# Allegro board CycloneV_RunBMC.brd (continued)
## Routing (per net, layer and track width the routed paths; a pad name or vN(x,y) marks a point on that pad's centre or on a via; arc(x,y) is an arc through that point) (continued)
EMMC_SMC_DAT0_CONN: length 65.5
  TOP w0.104: JT1.12 v1(66.26,49.18) ; v1(14.17,36.27) 14.24,36.2 14.38,36.2 14.48,36.1 RT139.1
  L8-SIG w0.076: v1(14.17,36.27) 14.17,36.38 14.65,36.86 14.65,46.05 16.31,47.71 49.33,47.71 49.69,48.06 65.14,48.06 v1(66.26,49.18)
EMMC_SMC_DAT0_R: length 1.6
  TOP w0.104: v1(12.98,32.47) 12.98,32.86 12.88,32.96 12.56,32.96 RT16.2
  BOTTOM w0.127: UB4.K2 v1(12.98,32.47)
EMMC_SMC_DAT1: length 41.6
  TOP w0.127: UT7.Y19 v1(33.97,23.2)
  L10-SIG w0.076: v1(16.83,23.81) 16.73,23.81 16.31,24.23 16.2,24.23 15.44,23.46 15.33,23.46 15.22,23.56 15.22,23.67 15.99,24.44 15.99,24.55 15.88,24.66 15.77,24.66 15,23.89 14.9,23.89 14.79,24 14.79,24.1 15.56,24.87 15.56,24.98 15.18,25.35 14.42,25.35 13.91,24.85 13.91,24.62 13.99,24.55 14.5,24.55 14.57,24.47 14.57,24.32 14.5,24.24 13.99,24.24 13.91,24.16 13.91,23.32 14.09,23.14 16.1,23.14 16.3,22.94 17.67,22.94 17.82,22.79 18.08,22.79 18.15,22.87 18.15,23.32 18.23,23.4 18.38,23.4 18.46,23.32 18.46,22.87 18.53,22.79 18.69,22.79 18.76,22.87 18.76,23.32 18.84,23.4 18.99,23.4 19.07,23.32 19.07,22.87 19.14,22.79 22.08,22.79 22.16,22.87 22.16,23.35 22.23,23.42 22.38,23.42 22.46,23.35 22.46,22.87 22.54,22.79 22.69,22.79 22.77,22.87 22.77,23.35 22.84,23.42 22.99,23.42 23.07,23.35 23.07,22.87 23.15,22.79 26.44,22.79 26.52,22.87 26.52,23.5 26.6,23.58 26.75,23.58 26.82,23.5 26.82,22.87 26.9,22.79 28.92,22.79 29.22,22.5 29.22,22.39 28.93,22.1 28.93,21.99 29.04,21.89 29.15,21.89 29.43,22.17 29.54,22.17 29.69,22.03 33.32,22.03 33.55,22.26 33.55,22.78 v1(33.97,23.2)
  BOTTOM w0.112: v1(16.83,23.81) 16.39,23.36 RB84.1 15.53,23.55 RB143.1
EMMC_SMC_DAT1_R: length 41
  BOTTOM w0.112: UB4.N2 13.22,29.97 13.58,30.33 13.58,35.66 13.69,35.77 15.58,35.77 15.72,35.63 15.72,35.39 15.6,35.28 14.43,35.28 14.32,35.17 14.32,34.95 14.43,34.83 15.6,34.83 15.72,34.72 15.72,34.5 15.6,34.39 14.43,34.39 14.32,34.28 14.32,34.05 14.43,33.94 15.6,33.94 15.72,33.83 15.72,33.6 15.6,33.49 14.43,33.49 14.32,33.38 14.32,33.16 14.43,33.05 15.6,33.05 15.72,32.93 15.72,32.65 15.83,32.54 16.34,32.54 16.45,32.42 16.45,32.2 16.34,32.09 15.83,32.09 15.72,31.98 15.72,31.75 15.83,31.64 16.34,31.64 16.45,31.53 16.45,31.31 16.34,31.2 15.83,31.2 15.72,31.08 15.72,30.01 15.83,29.9 16.8,29.9 16.91,29.79 16.91,29.57 16.8,29.45 15.83,29.45 15.72,29.34 15.72,29.12 15.83,29.01 16.8,29.01 16.91,28.89 16.91,28.67 16.8,28.56 15.83,28.56 15.72,28.45 15.72,28.22 15.83,28.11 16.8,28.11 16.91,28 16.91,27.78 16.8,27.67 15.83,27.67 15.72,27.55 15.72,26.74 15.6,26.63 14.58,26.63 14.47,26.51 14.47,26.29 14.58,26.18 15.6,26.18 15.72,26.07 15.72,25.84 15.6,25.73 14.58,25.73 14.47,25.62 14.47,25.4 14.58,25.28 15.6,25.28 15.72,25.17 RB84.2
EMMC_SMC_DAT2: length 80
  TOP w0.104: RT11.1 11.5,34.34 11.52,34.31 RT15.1 11.08,33.88 10.97,33.77 v1(10.97,33.41)
  TOP w0.127: UT7.AE25 v1(37.97,28)
  L3-SIG w0.076: v1(37.97,28) 38.55,28 40.18,29.62 40.18,31.81 41.45,33.08 43.68,33.08 45.38,34.78 45.38,42.88 44.47,43.8 44.47,46.84 43.76,47.55 13.99,47.55 10.43,44 10.43,39 10.36,38.92 8.65,38.92 8.58,38.85 8.58,38.69 8.65,38.62 10.36,38.62 10.43,38.54 10.43,38.39 10.36,38.31 8.65,38.31 8.58,38.24 8.58,38.08 8.65,38.01 10.36,38.01 10.43,37.93 10.43,33.95 v1(10.97,33.41)
EMMC_SMC_DAT2_R: length 1.6
  TOP w0.104: RT15.2 11.52,32.55 11.6,32.47 v1(11.98,32.47)
  BOTTOM w0.127: UB4.K3 v1(11.98,32.47)
EMMC_SMC_DAT3: length 79.1
  TOP w0.104: v1(12.84,26.44) 12.45,26.44 12.36,26.53 RT41.1 12.01,26.99 RT43.1
  TOP w0.127: UT7.Y17 v1(33.95,21.58)
  L10-SIG w0.076: v1(33.95,21.58) 33.56,21.19 31.18,21.19 31.1,21.11 31.1,20.68 31.03,20.6 30.88,20.6 30.8,20.68 30.8,21.11 30.72,21.19 29.53,21.19 29.45,21.11 29.45,20.71 29.38,20.63 29.22,20.63 29.15,20.71 29.15,21.11 29.07,21.19 25.35,21.19 25.27,21.27 25.27,21.8 25.2,21.87 25.04,21.87 24.97,21.8 24.97,21.27 24.89,21.19 22.74,21.19 22.67,21.27 22.67,21.7 22.59,21.77 22.44,21.77 22.36,21.7 22.36,21.27 22.29,21.19 22.13,21.19 22.06,21.27 22.06,21.7 21.98,21.77 21.83,21.77 21.75,21.7 21.75,21.27 21.68,21.19 18.31,21.19 18.23,21.11 17.29,21.11 17.06,21.34 16.4,21.34 16.05,20.99 15.28,20.99 15.06,20.76 15.06,19.89 14.78,19.61 14.41,19.61 14.33,19.69 14.33,22.41 14.26,22.48 14.1,22.48 14.03,22.41 14.03,19.69 13.95,19.61 13.8,19.61 13.72,19.69 13.72,22.41 13.65,22.48 13.5,22.48 13.42,22.41 13.42,19.69 13.34,19.61 13.19,19.61 13.11,19.69 13.11,22.41 13.04,22.48 12.89,22.48 12.81,22.41 12.81,19.69 12.73,19.61 12.58,19.61 12.5,19.69 12.5,22.41 12.43,22.48 12.28,22.48 12.2,22.41 12.2,19.69 12.12,19.61 11.97,19.61 11.9,19.69 11.9,22.41 11.82,22.48 11.67,22.48 11.59,22.41 11.59,19.69 11.51,19.61 11.22,19.61 11.04,19.79 11.04,21.42 10.86,21.6 10.66,21.6 10.59,21.68 10.59,21.83 10.66,21.91 10.86,21.91 10.94,21.98 10.94,22.13 10.86,22.21 10.66,22.21 10.59,22.29 10.59,22.44 10.66,22.52 10.86,22.52 10.94,22.59 10.94,22.74 10.86,22.82 10.66,22.82 10.59,22.9 10.59,23.05 10.66,23.13 10.86,23.13 10.94,23.2 10.94,24.52 10.89,24.57 10.89,25 10.81,25.08 10.03,25.08 9.95,25.16 9.95,25.31 10.03,25.38 10.81,25.38 10.89,25.46 10.89,25.61 10.81,25.69 10.03,25.69 9.95,25.77 9.95,25.92 10.03,25.99 10.81,25.99 10.89,26.07 10.89,26.22 10.81,26.3 10.03,26.3 9.95,26.37 9.95,26.53 10.03,26.6 10.81,26.6 10.89,26.68 10.89,26.78 11.09,26.98 11.96,26.98 12.03,26.9 12.03,25.35 12.11,25.28 12.26,25.28 12.34,25.35 12.34,26.9 12.41,26.98 12.63,26.98 12.84,26.77 v1(12.84,26.44)
EMMC_SMC_DAT3_R: length 2.5
  TOP w0.104: RT41.2 12.46,27.98 12.46,29 v1(11.98,29.47)
  BOTTOM w0.127: UB4.N3 v1(11.98,29.47)
EMMC_SMC_DAT4: length 80.2
  TOP w0.104: v1(6.98,30.68) 7.47,30.18 RT27.1 7.49,30.12 RT21.1
  TOP w0.127: UT7.Y18 v1(33.98,22.41)
  L3-SIG w0.076: v1(33.98,22.41) 33.6,22.79 32.27,22.79 32.03,22.55 32.03,22.39 31.7,22.06 31.53,22.06 31.23,21.75 31.23,21.31 30.14,20.22 29.15,20.22 28.82,20.55 28.82,20.86 28.49,21.19 24.2,21.19 23.93,21.46 23.93,23.35 23.68,23.6 22.27,23.6 21.48,24.39 18.46,24.39 18.31,24.24 16.29,24.24 16.21,24.31 16.21,24.88 16.29,24.96 16.94,24.96 17.01,25.04 17.01,25.19 16.94,25.27 16.29,25.27 16.21,25.34 16.21,25.49 16.29,25.57 16.94,25.57 17.01,25.65 17.01,25.8 16.94,25.88 16.29,25.88 16.21,25.95 16.21,27.18 16.14,27.26 15.98,27.26 15.91,27.18 15.91,24.29 15.83,24.21 15.68,24.21 15.6,24.29 15.6,27.18 15.53,27.26 15.37,27.26 15.3,27.18 15.3,24.29 15.22,24.21 15.07,24.21 14.99,24.29 14.99,27.18 14.92,27.26 14.76,27.26 14.69,27.18 14.69,24.29 14.61,24.21 13.63,24.21 12.57,25.28 12.28,25.28 12.21,25.35 12.21,26.12 12.13,26.19 11.98,26.19 11.9,26.12 11.9,25.35 11.83,25.28 10.6,25.28 10.52,25.35 10.52,25.58 10.44,25.66 10.29,25.66 10.21,25.58 10.21,25.35 10.14,25.28 9.99,25.28 9.91,25.35 9.91,25.58 9.83,25.66 9.68,25.66 9.61,25.58 9.61,25.35 9.53,25.28 9.38,25.28 9.3,25.35 9.3,25.58 9.22,25.66 9.07,25.66 9,25.58 9,25.35 8.92,25.28 8.5,25.28 7.82,25.96 7.13,25.96 7,26.09 7,26.5 6.75,26.75 5.94,26.75 5.86,26.83 5.86,27.49 5.79,27.56 5.63,27.56 5.56,27.49 5.56,26.83 5.48,26.75 5.33,26.75 5.25,26.83 5.25,27.49 5.18,27.56 5.02,27.56 4.95,27.49 4.95,26.83 4.87,26.75 4.34,26.75 3.9,27.18 3.9,27.8 3.98,27.88 4.59,27.88 4.67,27.95 4.67,28.11 4.59,28.18 3.98,28.18 3.9,28.26 3.9,28.46 3.98,28.54 5.1,28.54 5.17,28.61 5.17,28.77 5.1,28.84 3.98,28.84 3.9,28.92 3.9,29.07 3.98,29.15 5.1,29.15 5.17,29.22 5.17,29.38 5.1,29.45 3.98,29.45 3.9,29.53 3.9,29.68 3.98,29.76 5.1,29.76 5.17,29.83 5.17,29.99 5.1,30.06 3.98,30.06 3.9,30.14 3.9,30.46 4.39,30.94 6.71,30.94 v1(6.98,30.68)
EMMC_SMC_DAT4_R: length 1.6
  TOP w0.104: RT27.2 6.58,29.63 6.72,29.5 v1(6.96,29.5)
  BOTTOM w0.127: v1(6.96,29.5) UB4.N8
EMMC_SMC_DAT5: length 90.9
  TOP w0.104: v1(9.31,26.89) 8.91,27.29 8.91,27.89 9.14,28.12 9.14,31.86 8.32,32.67 8.32,33.13 8.08,33.37 RT98.1 7.26,33.37 RT18.1
  TOP w0.127: UT7.AB23 v1(35.55,26.38)
  L5-SIG w0.076: v1(35.55,26.38) 35.98,26.81 36.62,26.81 36.8,26.99 36.8,27.34 37.07,27.62 38.17,27.62 38.6,28.05 40.68,28.05 40.84,27.89 42.31,27.89 44.22,29.8 44.22,32.32 45.05,33.15 45.05,35.44 45.86,36.25 45.86,40.39 46.46,40.98 46.46,44.17 45.74,44.89 45.74,46.28 44.82,47.21 16.23,47.21 14.04,45.01 12.82,45.01 10.46,42.65 10.46,28.04 v1(9.31,26.89)
EMMC_SMC_DAT5_R: length 1.3
  TOP w0.104: RT18.2 6.08,32.57 v1(5.99,32.47)
  BOTTOM w0.127: UB4.K8 v1(5.99,32.47)
EMMC_SMC_DAT6: length 84.7
  TOP w0.104: RT36.1 7.41,27.72 ; 7.41,27.72 7.42,27.73 RT30.1 ; 7.41,27.72 7.37,27.72 v1(7.01,28.08)
  TOP w0.127: UT7.AA24 v1(33.99,26.42)
  L3-SIG w0.076: v1(33.99,26.42) 34.27,26.7 34.28,26.7 34.34,26.76 34.34,27.27 34.63,27.55 38.44,27.55 42.05,31.17 42.61,31.17 45.69,34.24 45.69,42.93 45.56,43.06 45.56,43.62 45.79,43.85 45.79,45.95 43.96,47.78 13.86,47.78 8.93,42.86 8.93,41.48 7.48,40.03 7.48,28.55 v1(7.01,28.08)
EMMC_SMC_DAT6_R: length 1.8
  TOP w0.104: v1(5.92,29.54) 5.92,29.05 6.04,28.94 RT30.2
  BOTTOM w0.127: v1(5.92,29.54) UB4.N9
EMMC_SMC_DAT7: length 82.6
  TOP w0.104: RT99.1 6.5,34.38 6.99,33.89 RT13.1 7.42,33.81 7.55,33.94 8.2,33.94 8.58,33.55 8.58,32.85 9.44,32 9.44,27.95 9.32,27.82 v1(9.32,27.42)
  TOP w0.127: UT7.V16 v1(32.38,20.81)
  L10-SIG w0.076: v1(9.32,27.42) 8.21,27.42 7.92,27.13 7.92,26.87 7.99,26.79 8.68,26.79 8.76,26.72 8.76,26.56 8.68,26.49 7.99,26.49 7.92,26.41 7.92,26.26 7.99,26.18 8.68,26.18 8.76,26.11 8.76,25.96 8.68,25.88 7.99,25.88 7.92,25.8 7.92,25.1 7.99,25.02 8.37,25.02 8.44,25.1 8.44,25.48 8.52,25.56 8.67,25.56 8.75,25.48 8.75,25.1 8.83,25.02 9.54,25.02 9.62,24.95 9.62,24.52 9.67,24.47 9.98,24.47 10.08,24.36 10.08,23.42 9.96,23.3 8.28,23.3 7.87,22.89 7.87,22.66 7.94,22.58 9.85,22.58 9.92,22.5 9.92,22.35 9.85,22.27 7.94,22.27 7.87,22.2 7.87,22.05 7.94,21.97 9.85,21.97 9.92,21.89 9.92,21.74 9.85,21.66 7.94,21.66 7.87,21.59 7.87,21.44 7.94,21.36 9.85,21.36 9.92,21.28 9.92,21.13 9.85,21.06 7.94,21.06 7.87,20.98 7.87,20.45 8.05,20.27 8.98,20.27 9.98,19.28 10.3,19.28 10.37,19.21 10.37,17.94 10.45,17.86 10.6,17.86 10.68,17.94 10.68,19.21 10.75,19.28 10.9,19.28 10.98,19.21 10.98,17.94 11.06,17.86 11.21,17.86 11.29,17.94 11.29,19.21 11.36,19.28 11.51,19.28 11.59,19.21 11.59,17.94 11.67,17.86 11.82,17.86 11.9,17.94 11.9,19.21 11.97,19.28 12.12,19.28 12.2,19.21 12.2,17.94 12.28,17.86 12.43,17.86 12.51,17.94 12.51,19.21 12.58,19.28 12.73,19.28 12.81,19.21 12.81,17.94 12.89,17.86 13.04,17.86 13.11,17.94 13.11,19.21 13.19,19.28 13.34,19.28 13.42,19.21 13.42,17.94 13.5,17.86 13.65,17.86 13.72,17.94 13.72,19.21 13.8,19.28 13.95,19.28 14.03,19.21 14.03,17.94 14.11,17.86 14.26,17.86 14.33,17.94 14.33,19.21 14.41,19.28 15.94,19.28 17.43,20.77 18.04,20.77 18.43,20.38 31.95,20.38 v1(32.38,20.81)
EMMC_SMC_DAT7_R: length 2.8
  TOP w0.104: v1(4.99,32.47) 5.58,33.07 5.58,33.73 5.67,33.81 RT13.2
  BOTTOM w0.127: UB4.K9 v1(4.99,32.47)
EMMC_STRB_R: length 1.7
  TOP w0.104: v1(9.9,32.56) 9.9,32.95 9.73,33.11 RT14.1
  BOTTOM w0.127: UB4.K5 v1(9.9,32.56)
FAN_PWM0: length 18.8
  TOP w0.104: v1(16.81,9.91) 16.54,9.64 16.54,9.62 16.39,9.47 EUT3.20
  L5-SIG w0.076: v1(7.38,5.9) 7.37,5.9 7,6.27 7,6.73 7.01,6.74 8.18,7.92 8.77,7.92 8.91,7.78 11.32,7.78 11.88,8.34 11.88,8.67 12.79,9.58 16.48,9.58 v1(16.81,9.91)
  BOTTOM w0.112: v1(7.38,5.9) 6.93,5.44 6.93,4.52 7.17,4.28 7.42,4.28 7.68,4.02 JT3.26
FAN_PWM1: length 16.3
  TOP w0.104: EUT3.18 v1(16.35,8.67)
  L5-SIG w0.076: v1(7.38,6.43) 7.38,6.78 8.24,7.63 8.56,7.63 8.69,7.5 11.63,7.5 12.31,8.18 15.87,8.18 v1(16.35,8.67)
  BOTTOM w0.112: JT3.28 8.23,1.62 8.23,4.74 7.79,5.18 7.79,6.16 7.52,6.43 v1(7.38,6.43)
FAN_PWM2: length 16.2
  TOP w0.104: v1(8.42,6.69) 8.02,6.28 8.02,5.09 8.22,4.89 8.22,3.17 8.16,3.11 7.93,2.87 JT3.27 ; EUT3.16 16.11,7.87 16.22,7.75 16.23,7.75 16.28,7.7 16.55,7.7 v1(16.96,8.11)
  L5-SIG w0.076: v1(16.96,8.11) 16.58,7.73 16.05,7.73 15.53,7.21 8.95,7.21 v1(8.42,6.69)
FAN_PWM3: length 13.2
  TOP w0.104: v1(15.33,6.78) 15.33,6.79 15.33,6.94 15.23,7.04 14.98,7.04 14.88,6.95 EUT3.14
  L5-SIG w0.076: v1(8.41,6.1) 9.19,6.89 12.53,6.89 12.64,6.78 v1(15.33,6.78)
  BOTTOM w0.112: v1(8.41,6.1) 8.27,6.1 8.03,5.86 8.03,5.28 8.48,4.83 8.48,3.17 8.68,2.97 JT3.30
FAN_PWM4: length 11.5
  TOP w0.104: v1(8.42,5.54) 8.46,5.5 8.46,2.91 8.43,2.88 JT3.29 ; v1(14.08,6.09) EUT3.12
  L5-SIG w0.076: v1(8.42,5.54) 9.25,4.71 11.41,4.71 11.6,4.91 11.6,5.39 11.88,5.67 13.66,5.67 v1(14.08,6.09)
FAN_PWM5: length 10.9
  TOP w0.104: v1(13.3,6.08) 13.3,6.08 13.28,6.1 EUT3.10
  BOTTOM w0.112: v1(13.3,6.08) 12.49,6.89 9.01,6.89 8.81,6.69 8.81,6.53 8.81,6.52 8.81,5.05 8.72,4.96 8.72,3.32 9.18,2.86 JT3.32
FAN_TACH0: length 10.9
  TOP w0.104: v1(16.99,8.67) 16.59,9.07 EUT3.19
  L5-SIG w0.076: v1(16.99,8.67) 18.33,7.32 19.27,7.32 19.91,6.69 19.91,5.28 v1(20.31,4.88)
  BOTTOM w0.112: JT3.78 20.68,2.88 20.85,3.05 20.85,3.95 20.31,4.49 v1(20.31,4.88)
FAN_TACH1: length 11.3
  TOP w0.104: EUT3.17 16.22,8.27 16.35,8.13 v1(16.38,8.13)
  BOTTOM w0.112: v1(16.38,8.13) 16.02,7.77 16.02,6.99 17.37,5.64 18.1,5.64 18.45,5.3 20.51,5.3 20.82,4.99 20.82,4.43 21.18,4.07 JT3.80
FAN_TACH2: length 11.9
  TOP w0.104: v1(16.41,7.3) 16.4,7.3 16.23,7.47 EUT3.15
  BOTTOM w0.112: JT3.82 21.68,2.81 21.48,3 21.48,4.09 21.78,4.39 21.78,5.66 21.28,6.17 20.21,6.17 19.68,5.64 18.59,5.64 18.32,5.91 17.48,5.91 17.01,6.38 17.01,6.7 v1(16.41,7.3)
FAN_TACH3: length 13.3
  TOP w0.104: v1(21.91,3.71) 21.91,4.94 21.53,5.31 20.21,5.31 19.98,5.54 19.98,6.57 19.63,6.91 18.16,6.91 18.16,6.92 17.9,6.92 ; EUT3.13 14.48,6.31 14.57,6.23
  TOP w0.114: 14.57,6.23 15.54,6.23 16,6.69 16.35,6.69 16.58,6.92 17.9,6.92
  BOTTOM w0.112: JT3.84 22.18,2.89 22.31,3.02 22.31,3.52 22.12,3.71 v1(21.91,3.71)
FAN_TACH4: length 16.2
  TOP w0.104: EUT3.11 13.68,5.29 14.09,4.88 16.4,4.88 17.47,5.95 v1(17.47,6.5)
  BOTTOM w0.112: v1(17.47,6.5) 17.52,6.5 17.62,6.41 17.62,6.37 17.84,6.15 18.48,6.15 18.63,6 19.59,6 20.02,6.43 21.48,6.43 22.04,5.87 22.04,4.83 22.57,4.3 22.57,3.12 22.68,3.02 JT3.86
FAN_TACH5: length 17.6
  TOP w0.104: EUT3.9 12.88,5.76 13.99,4.65 16.5,4.65 16.5,4.65 16.55,4.65 18,6.1 v1(18,6.53)
  BOTTOM w0.112: v1(18,6.53) 18.33,6.86 21.89,6.86 23.14,5.61 23.14,3.72 23.36,3.51 23.36,3.08 23.18,2.9 JT3.88
FM_B2B_BUFFER_OE3_N: length 38.8
  TOP w0.104: v1(52.42,25.51) 52.42,25.56 UT4.B12
  L5-SIG w0.076: v1(40.48,4.15) 40.5,4.15 40.87,4.51 41.56,4.51 41.88,4.19 41.88,2.29 42.28,1.89 43.83,1.89 44.58,2.63 44.58,3.46 44.29,3.75 44.29,5.66 45.61,6.98 45.61,13.48 49,16.87 49.93,16.87 54.1,21.04 54.1,22.76 53.52,23.34 53.52,24.41 v1(52.42,25.51)
  BOTTOM w0.112: v1(40.48,4.15) 40.25,4.15 39.93,3.82 39.93,3.02 39.92,3.02 39.92,3 39.64,2.72 39.64,1.61 JT3.146
FM_B2B_BUFFER_OE4_N: length 43.4
  TOP w0.104: v1(53.41,25.53) 53.41,25.55 UT4.B11
  L5-SIG w0.076: v1(53.41,25.53) 53.01,25.93 52.19,25.93 51.83,25.58 51.83,24.97 52.83,23.98 52.83,23.46 53.29,22.99 53.29,20.71 49.75,17.18 48.96,17.18 45.33,13.54 45.33,7.04 44.05,5.76 44.05,3.65 44.34,3.36 44.34,2.73 43.72,2.11 42.54,2.11 42.13,2.52 42.13,4.39 41.18,5.34 39.92,5.34 39.71,5.13 39.71,4.94 39.72,4.93 v1(39.72,4.88)
  BOTTOM w0.112: 39.44,4.61 37.9,4.61 37.18,3.89 JT3.144
  BOTTOM w0.114: 39.24,4.61 39.24,4.6 ; v1(39.72,4.88) 39.44,4.6
FM_BIOS_POST_CMPLT_N: length 31.8
  TOP w0.127: v1(17.42,21.54) 17.42,21.62 17.8,22.01 UT7.A18
  L3-SIG w0.076: v1(17.42,21.54) 16.93,21.54 16.48,21.09 16.48,20.61 16.48,20.6 16.48,19.74 16.07,19.33 14.37,19.33 13.14,18.11 13.14,16.74 12.24,15.84 12.24,8.79 11.75,8.31 11.75,5.84 11.77,5.83 11.77,5.51 11.75,5.5 11.75,3.26 12.01,3 12.03,3 12.59,2.44 17.53,2.44 17.62,2.53 17.62,2.6 v1(18.18,3.16)
  BOTTOM w0.112: v1(18.18,3.16) JT3.68
FM_BMC_HBIN: length 26.3
  TOP w0.089: UT7.E8 v1(21.96,14.39)
  TOP w0.104: JT3.141 36.43,2.99 36.32,3.1 36.32,3.13 v1(36.29,3.15)
  L3-SIG w0.076: v1(36.29,3.15) 36.29,3.13 36.05,2.89 36.05,2.76 35.2,1.91 30.13,1.91 29.11,2.92 29.11,4.41 28.48,5.05 28.48,6.42 27.7,7.2 27.2,7.7 27.2,11.56 26.82,11.94 24.23,11.94 21.96,14.21 v1(21.96,14.39)
FM_BMC_HBOUT: length 29.7
  TOP w0.089: UT7.D8 v1(21.17,13.62)
  TOP w0.104: v1(36.29,3.69) 36.75,3.69 36.93,3.51 JT3.143
  L3-SIG w0.076: v1(21.17,13.62) 21.56,14.01 21.56,14.69 21.76,14.89 22.12,14.89 22.62,14.38 22.62,14.03 24.25,12.4 27.1,12.4 27.96,11.54 27.96,7.45 29.36,6.05 29.36,3.88 29.34,3.86 29.34,3.01 30.15,2.19 35.01,2.19 35.92,3.11 35.92,3.31 36.29,3.67 v1(36.29,3.69)
FM_BMC_ON: length 89.9
  TOP w0.104: JT3.109 28.43,2.65 28.14,2.95 28.14,3.29 28.39,3.55 v1(28.39,3.63)
  TOP w0.127: UT4.F10 v1(54.38,29.52)
  L3-SIG w0.076: v1(28.39,3.63) 28.13,3.36 28.13,2.97 29.69,1.4 35.86,1.4 36.96,2.51 36.96,4.06 37.78,4.87 38.84,4.87 40.19,3.52 40.19,2.28 41.7,0.77 65.02,0.77 67.02,2.77 67.02,3.41 68.79,5.17 68.79,11.97 68.64,12.12 68.64,16.65 67.94,17.35 67.83,17.39 67.6,17.55 67.4,17.75 67.24,17.98 67.2,18.09 66.49,18.8 66.49,21.57 66.81,21.9 66.81,25.74 66.49,26.07 66.49,28.89 65.96,29.42 65.93,29.45 63.87,29.45 63.52,29.1 62.43,29.1 62.11,29.42 60.77,29.42 60.53,29.17 54.73,29.17 v1(54.38,29.52)
FM_BMC_ONCTL_R_N: length 29.2
  TOP w0.127: UT7.H16 v1(23.58,20.81)
  L8-SIG w0.076: v1(23.58,20.81) 23.26,20.81 22.81,20.36 22.28,20.36 21.02,19.11 20.24,19.11 20.02,18.89 20.02,18.3 19.7,17.99 18.08,17.99 14.98,14.89 14.98,13.85 14.4,13.26 13.63,13.26 12.34,11.97 12.34,10.1 11.64,9.4 11.64,5.93 11.36,5.64 v1(11.22,5.64)
  BOTTOM w0.112: 11.25,5.64 11.37,5.52 11.37,5.46 11.58,5.25 11.58,4.91 11.35,4.68 10.41,4.68 10.1,4.37 10.1,3.03 10.18,2.95 JT3.36
  BOTTOM w0.114: v1(11.22,5.64) 11.65,5.64 RB82.2
FM_BMC_PWRBTN_OUT_N: length 42.9
  TOP w0.089: 40.73,11.26 40.56,11.44 40.56,11.77 40.3,12.02 39.57,12.02 UT7.AG6
  TOP w0.104: v1(39.92,6.91) 40.39,7.38 RT108.2 41.14,7.46 41.14,8.84 41.37,9.07 41.37,10.62 40.73,11.26
  L8-SIG w0.076: v1(11.37,3.54) 11.37,2.25 11.88,1.73 32.61,1.73 33.42,2.55 33.42,3.56 34.18,4.32 34.18,4.81 34.89,5.52 36.29,5.52 37.3,6.52 39.53,6.52 v1(39.92,6.91)
  BOTTOM w0.112: JT3.40 11.18,2.97 11.37,3.15 v1(11.37,3.54)
FM_BOARD_ID: length 44.1
  TOP w0.104: v1(51.91,6.12) 53.08,4.95 53.08,3.79 53.21,3.66 53.21,3.1 53.43,2.88 JT3.201
  TOP w0.127: UT4.F12 v1(52.38,29.52)
  L8-SIG w0.076: v1(51.91,6.12) 51.91,6.43 52.01,6.53 52.02,6.53 52.5,7.02 52.5,8.73 52.42,8.81 52.42,9.68 52.9,10.17 52.9,11.87 51.94,12.83 51.94,14.66 50.91,15.69 50.91,18.2 53.41,20.71 53.41,20.86 53.21,21.06 52.22,21.06 51,22.28 51,23.81 50.85,23.95 50.85,28.55 51.18,28.88 51.74,28.88 v1(52.38,29.52)
  BOTTOM w0.112: v1(52.38,29.52) 52,29.9 51.07,29.9 50.79,29.62 50.41,29.62 49.17,28.38 49.17,27.21 47.53,25.57 RB86.1
FM_C5_BSEL0: length 11.5
  TOP w0.114: v1(15.59,19.96) 15.59,19.69 RB79.2
  TOP w0.127: UT7.J17 v1(24.38,21.61)
  L8-SIG w0.076: v1(24.38,21.61) 23.98,22 18.66,22 18.42,21.76 18.42,21.32 18.15,21.06 17.54,21.06 16.44,19.96 v1(15.59,19.96)
FM_C5_BSEL1: length 1.5
  TOP w0.127: UT7.A6 v1(17.98,12.01)
  BOTTOM w0.114: v1(17.98,12.01) 17.73,12.01 RT20.1
FM_C5_BSEL2: length 2.6
  TOP w0.127: UT7.D15 v1(20.38,20.01)
  BOTTOM w0.114: v1(20.38,20.01) 19.98,20.4 19.14,20.4 18.97,20.57 RT78.1
FM_C5_CONF_DONE: length 45.5
  TOP w0.104: v1(47.49,35.77) 47.9,35.77 48.15,35.51 49.4,35.51 49.88,36 UT4.M15
  TOP w0.127: UT7.J8 v1(24.38,13.61)
  L8-SIG w0.076: v1(24.38,13.61) 24.38,13.8 24,14.18 24,15.47 24.12,15.6 24.5,15.6 25.35,16.45 28.6,16.45 28.85,16.69 28.85,19.21 29.19,19.55 29.19,22.32 29.64,22.77 35.43,22.77 36.26,23.6 37.46,23.6 37.7,23.84 38.82,23.84 39.41,24.44 41.22,24.44 43.94,27.16 43.94,31.63 45.32,33.01 47.35,33.01 47.69,33.36 47.69,35.57 v1(47.49,35.77)
  BOTTOM w0.112: RT28.1 47.06,35.34 v1(47.49,35.77)
FM_C5_CONFIG_N: length 51.3
  TOP w0.127: UT7.F7 v1(21.98,12.81) ; UT4.L12 v1(52.42,34.55)
  L3-SIG w0.076: v1(52.42,34.55) 51.96,35.01 49.35,35.01 48.05,36.3 v1(47.49,36.3)
  L8-SIG w0.076: v1(47.49,36.3) 45.81,36.3 45.21,35.69 45.21,34.65 44.09,33.53 44.09,32.67 42.69,31.27 42.69,26.83 41.11,25.25 36.3,25.25 35.49,24.43 29.67,24.43 29.08,23.83 29.08,23.27 28.65,22.85 28.22,22.85 27.96,22.59 27.96,19.69 27.4,19.13 26.79,19.13 26.36,18.7 26.36,18.17 26.17,17.98 23.44,17.98 23.16,17.7 23.16,16 22.72,15.57 22.72,15.57 22.37,15.22 22.37,13.2 v1(21.98,12.81)
  BOTTOM w0.112: v1(52.42,34.55) 52.42,34.94 52.26,35.1 RB71.1
FM_C5_DEV_OE_N: length 1.2
  TOP w0.127: UT7.AC24 v1(36.38,27.21)
  BOTTOM w0.254: v1(36.38,27.21) 36.25,27.08 RB75.1
FM_C5_FPGA_AS_DATA0: length 41.4
  TOP w0.127: UT7.AD7 v1(37.18,12.81)
  L3-SIG w0.076: v1(50.77,12.28) 49.91,12.28 49.24,11.61 46.04,11.61 44.44,13.21 41.9,13.21 41.62,13.49 39.29,13.49 39.01,13.21 37.58,13.21 v1(37.18,12.81)
  L8-SIG w0.076: v1(50.77,12.28) 50.2,12.85 50.2,16.78 50.36,16.95 50.36,20.83 49.39,21.81 49.39,23.7 49.8,24.11 49.8,24.61 49.26,25.16 49.23,25.16 49.02,25.37 49.02,28.04 v1(48.3,28.76)
  BOTTOM w0.112: RB69.2 48.41,35.9 47.97,35.46 47.97,29.09 v1(48.3,28.76)
FM_C5_FPGA_AS_DATA0_R: length 1.4
  TOP w0.127: UT4.M14 v1(50.42,35.56)
  BOTTOM w0.112: v1(50.42,35.56) 50.12,35.56 RB69.1
FM_C5_FPGA_DCLK: length 32.5
  TOP w0.104: v1(46.07,34.07) 46.37,34.37 46.37,34.98 RT37.2
  TOP w0.127: UT7.AA8 34.91,14.01 35.01,13.9 v1(35.01,13.51)
  L5-SIG w0.076: v1(46.07,34.07) 46.07,31.35 45.31,30.59 45.31,29.37 43.03,27.09 39.91,27.09 39.39,27.62 38.67,27.62 38.42,27.36 38.42,27.05 38.17,26.8 37.84,26.8 37.31,26.28 36.37,26.28 36.16,26.07 36.16,25.9 36,25.75 36,24.65 36.16,24.49 36.16,20.91 35.71,20.45 35.71,14.2 v1(35.01,13.51)
  BOTTOM w0.254: RB135.1 34.28,13.11 34.74,13.57 34.95,13.57 v1(35.01,13.51)
FM_C5_FPGA_DCLK_R: length 1.6
  TOP w0.104: RT37.1 47.33,35.02 UT4.L16
FM_C5_FPGA_MSEL0: length 54.8
  TOP w0.104: RT85.1 RT84.2 64.76,23.8 v1(64.66,23.91) 64.1,24.47 63.43,24.47 UT4.A2
  TOP w0.127: UT7.J10 v1(24.38,15.21)
  L8-SIG w0.076: v1(45.13,24.54) 45.13,24.8 44.82,25.1 44.09,25.1 43.78,24.8 42.7,24.8 41.55,23.65 37.9,23.65 37.62,23.36 37.62,23.05 37.38,22.81 36.52,22.81 35.69,21.98 29.69,21.98 29.51,21.8 29.51,19.23 29.15,18.88 29.15,16.03 28.74,15.62 25.01,15.62 24.59,15.21 v1(24.38,15.21)
  L10-SIG w0.076: v1(45.13,24.54) 45.52,24.93 61.35,24.93 61.82,24.47 61.82,23.45 62.1,23.17 64.46,23.17 64.66,23.37 v1(64.66,23.91)
FM_C5_FPGA_MSEL1: length 54.4
  TOP w0.104: UT4.A3 62.43,24.47 62.98,24.47 63.09,24.36 v1(63.09,23.61) RT83.1 RT73.2
  TOP w0.127: UT7.H9 v1(23.58,14.41)
  L8-SIG w0.076: v1(43.76,23.24) 43.76,23.25 43.73,23.25 43.58,23.4 42.65,23.4 41.26,22.01 41.26,21.98 40.5,21.21 36.24,21.21 35.63,20.6 35.63,20.55 35.43,20.35 35.43,19.79 35.22,19.59 31.16,19.59 30.37,18.8 30.37,14.99 30.19,14.81 29.76,14.81 29.2,14.25 29.2,13.77 28.54,13.11 24.36,13.11 23.97,13.5 23.97,13.8 23.58,14.19 v1(23.58,14.41)
  L10-SIG w0.076: v1(63.09,23.61) 63.09,24.22 62.16,25.15 44.26,25.15 43.76,24.64 v1(43.76,23.24)
FM_C5_FPGA_MSEL2: length 86
  TOP w0.104: v1(62.25,23.6) 62.25,23.52 62.33,23.44 RT75.1 61.61,23.03 RT76.2 61.59,24.31 UT4.A4
  TOP w0.127: UT7.G6 v1(22.78,12.01)
  L3-SIG w0.076: v1(22.78,12.01) 24,10.79 24,10.17 28.23,5.93 28.23,4.99 28.89,4.33 28.89,2.65 29.91,1.63 35.78,1.63 36.75,2.6 36.75,4.15 37.67,5.07 38.96,5.07 40.4,3.62 40.4,2.37 41.79,0.98 64.62,0.98 66.57,2.93 66.57,4.7 66.21,5.06 66.21,6.33 68.42,8.54 68.42,11.89 67.86,12.45 66.67,12.45 66.49,12.63 66.49,15.78 65.3,16.97 65.3,22.71 64.94,23.07 62.79,23.07 v1(62.25,23.6)
FM_C5_FPGA_MSEL3: length 45.8
  TOP w0.104: RT82.2 RT81.1 60.12,24.78 UT4.A5 59.86,25.02 v1(59.33,24.49)
  TOP w0.127: UT7.K10 v1(25.18,15.21)
  L8-SIG w0.076: v1(44.54,24.54) 44.52,24.52 42.89,24.52 41.15,22.77 37.83,22.77 37.62,22.56 37.62,22.33 37.33,22.05 36.18,22.05 35.31,21.17 30.89,21.17 29.84,20.12 29.84,19.16 29.38,18.7 29.38,15.48 28.75,14.85 25.54,14.85 v1(25.18,15.21)
  L10-SIG w0.076: v1(44.54,24.54) 45.12,23.96 47.62,23.96 47.82,24.17 50.84,24.17 51,24 55.08,24 55.8,24.72 58.88,24.72 59.11,24.49 v1(59.33,24.49)
FM_C5_FPGA_MSEL4: length 44.8
  TOP w0.104: UT4.A6 58.64,24.78 v1(58.64,24.36) RT79.2 RT80.1
  TOP w0.127: UT7.K9 v1(25.18,14.41)
  L8-SIG w0.076: v1(25.18,14.41) 25.56,14.03 28.62,14.03 29.62,15.02 29.62,18.56 30.14,19.08 30.14,20.02 30.55,20.43 34.97,20.43 36.34,21.8 37.53,21.8 37.78,22.05 40.86,22.05 42.72,23.91 43.64,23.91 v1(44.3,23.25)
  L10-SIG w0.076: v1(58.64,24.36) 55.82,24.36 55.27,23.81 50.93,23.81 50.76,23.98 49.21,23.98 48.23,22.99 44.56,22.99 v1(44.3,23.25)
FM_C5_INIT_DONE: length 25.7
  TOP w0.104: UT4.A8 56.58,24.72 RT87.2 55.99,22.8 v1(55.85,22.66)
  TOP w0.127: UT7.AA20 v1(34.78,24.01)
  L10-SIG w0.076: v1(34.78,24.01) 35.16,23.63 42.03,23.63 43,22.66 48.3,22.66 48.71,23.07 55.31,23.07 55.72,22.66 v1(55.85,22.66)
FM_C5_M10_RSVD<0>: length 31.8
  TOP w0.127: UT4.L9 55.88,35.07 56.33,35.51 v1(56.33,35.52) ; UT7.AB26 v1(34.79,28.02)
  L10-SIG w0.076: v1(34.79,28.02) 35.2,27.62 38.7,27.62 40.26,29.17 40.26,29.78 41.01,30.54 42.49,30.54 44.91,32.96 44.91,36.54 46.27,37.9 47.34,37.9 48.25,36.99 54.6,36.99 54.86,36.73 54.86,35.31 55.02,35.15 56.07,35.15 56.33,35.41 v1(56.33,35.52)
FM_C5_M10_RSVD<1>: length 30.4
  TOP w0.127: UT7.W20 33.15,23.98 33.19,23.98 33.22,24.01 v1(33.22,24.01) ; UT4.L10 v1(54.38,35.52)
  L10-SIG w0.076: v1(33.22,24.01) 32.84,24.4 32.84,25.05 33.01,25.23 40.68,25.23 44.16,28.71 44.16,28.94 46.75,31.53 46.75,34.68 47.08,35.01 52.7,35.01 53.21,35.52 v1(54.38,35.52)
FM_C5_M10_RSVD<2>: length 31.4
  TOP w0.104: UT4.M10 55.37,35.53 v1(55.37,35.52)
  TOP w0.127: UT7.AA26 v1(34.73,28.76)
  L10-SIG w0.076: v1(55.37,35.52) 55.72,35.87 55.72,36.81 55.44,37.09 55.14,37.09 54.91,37.32 54.91,37.65 54.6,37.95 47.75,37.95 47.49,38.21 45.94,38.21 44.57,36.84 44.57,32.92 42.44,30.79 40.63,30.79 40.02,30.18 40.02,29.38 39.02,28.38 35.11,28.38 v1(34.73,28.76)
FM_C5_M10_RSVD<3>: length 29.2
  TOP w0.104: UT4.M11 54.38,36.52 v1(54.38,36.52)
  TOP w0.127: v1(33.14,26.42) 33.15,26.42 33.19,26.42 UT7.Y24
  L10-SIG w0.076: v1(54.38,36.52) 53.99,36.12 48.76,36.12 48,35.36 46.7,35.36 46.48,35.13 46.48,31.55 41.65,26.73 40.76,26.73 40.02,25.99 33.57,25.99 v1(33.14,26.42)
FM_C5_STATUS_N: length 44
  TOP w0.104: UT4.L15 49.88,34.88 49.55,34.55 47.54,34.55 v1(47.29,34.3)
  TOP w0.127: UT7.H8 v1(23.58,13.61)
  L8-SIG w0.076: v1(47.29,34.3) 46.48,33.48 45.31,33.48 43,31.17 43,26.64 41.28,24.92 39.46,24.92 38.93,24.39 36.2,24.39 35.39,23.58 29.76,23.58 28.87,22.69 28.87,19.64 28.02,18.78 28.02,17.46 27.8,17.25 24.23,17.25 23.97,16.99 23.97,15.89 23.68,15.6 23.39,15.6 23.22,15.43 23.22,13.97 v1(23.58,13.61)
  BOTTOM w0.112: RT34.1 47.24,34.3 v1(47.29,34.3)
FM_CPLD_HOLD_N: length 27.7
  TOP w0.104: 34.8,6.99 34.8,5.64 34.59,5.43 34.38,5.43 ; RT123.2 34.26,4.41 33.7,3.85 33.7,3.11 33.8,3.01 33.8,3 33.93,2.87 JT3.131
  TOP w0.114: 34.38,5.43 RT123.2 ; v1(35.33,7.7) 34.8,7.17 34.8,6.99
  TOP w0.127: UT7.AC23 v1(35.55,25.58)
  L5-SIG w0.076: v1(35.55,25.58) 35.76,25.38 35.76,24.31 35.91,24.16 35.91,21.29 35.45,20.83 35.45,14.46 34.65,13.66 34.65,12.95 33.55,11.84 33.55,10.17 33.75,9.97 34.13,9.97 34.41,9.69 34.41,8.62 v1(35.33,7.7)
FM_CPU_BMC_MSMI_CATERR_LVT3_N: length 31.2
  TOP w0.104: v1(9.9,5.52) 9.9,3.41 10.43,2.88 JT3.37
  TOP w0.127: UT7.H17 v1(23.58,21.61)
  L8-SIG w0.076: v1(23.58,21.61) 22.1,21.61 21.74,21.24 21.74,20.73 21.41,20.4 18.56,20.4 18.15,20 17.46,20 16.82,19.36 14.62,19.36 13.86,18.6 13.86,16.03 11.86,14.03 11.86,10.3 11.02,9.46 11.02,7.73 10.25,6.97 9.87,6.97 9.52,6.61 9.52,5.9 v1(9.9,5.52)
FM_CPU_BMCINIT: length 35.8
  TOP w0.104: v1(51.34,4.91) 51.72,4.91 51.93,4.7 JT3.195
  TOP w0.127: UT7.AH22 v1(40.38,25.61)
  L3-SIG w0.076: v1(40.38,25.61) 41.9,25.61 42.39,26.09 47.16,26.09 47.72,25.53 v1(48.35,25.53)
  L8-SIG w0.076: v1(51.34,4.91) 51.34,5.4 50.89,5.85 50.89,7.02 50.38,7.53 50.38,8.08 50.59,8.29 50.59,10.54 49.96,11.18 49.96,12.58 49.36,13.17 49.36,16.43 50.12,17.19 50.12,20.62 49.39,21.35 49.39,21.37 48.63,22.14 48.63,23.11 49.02,23.5 49.02,24.87 v1(48.35,25.53)
FM_CPU_ERR2_LVT3_N: length 14.2
  TOP w0.104: JT3.79 20.93,3.61 20.72,3.82 19.88,3.82 19.04,4.65 19.04,5.62 19.48,6.05 v1(19.48,6.43)
  TOP w0.127: UT7.A7 v1(17.98,12.81)
  L3-SIG w0.076: v1(19.48,6.43) 19.48,6.91 19.17,7.22 19.17,12.2 18.97,12.4 18.39,12.4 v1(17.98,12.81)
FM_DEDI_IO3: length 37.1
  L5-SIG w0.076: v1(67.38,32.19) 67.35,32.19 67.04,31.88 66.47,31.88 65.83,32.52 65.83,35.21 66.36,35.74 66.95,35.74 66.98,35.77 v1(67.37,35.77) 67.37,36.95 66.26,38.05 59.84,38.05 57.47,35.69 57.47,35.18 56.7,34.41 56.7,31.23 56.05,30.59 56.05,24.49 56.54,24 56.54,23.26 56.33,23.05 55.11,23.05 v1(54.69,23.46)
  BOTTOM w0.112: TP8.1 67.91,31.65 v1(67.38,32.19) ; RB101.1 54.95,24 54.69,23.74 v1(54.69,23.46) ; RB18.2 v1(67.37,35.77)
FM_DS1818_EN: length 9.3
  BOTTOM w0.254: Q3L1.3 6.19,45.85 5.94,46.11 CB1.1 5.76,47.39 4.86,48.29 Q6A1.2 ; Q3L1.3 6.8,45.01 7.93,46.13 Q7A1.2 ; Q3L1.3 5,45.01 RB31.2
FM_DS1818_EN_G: length 2.9
  BOTTOM w0.254: Q3L1.5 7.46,44.36 7.2,44.1 7.2,43.92 7.42,43.71 Q3L1.6 8.97,43.71 8.98,43.72
FM_DUMP_ALERT_N: length 70.4
  TOP w0.104: v1(7.82,4.5) 7.92,4.4 7.92,3.2 7.43,2.71 JT3.25 ; UT4.A12 v1(52.88,24.52)
  L3-SIG w0.076: v1(46.86,24.34) 47.03,24.17 48.53,24.17 48.68,24.01 52.37,24.01 v1(52.88,24.52)
  L8-SIG w0.076: v1(7.82,4.5) 7.82,3.66 9.99,1.49 33.23,1.49 34.6,2.86 34.6,4.05 34.42,4.22 34.42,4.67 35.05,5.29 36.41,5.29 37.4,6.28 42.23,6.28 42.49,6.53 42.49,7.65 42.97,8.13 42.97,11.16 42.79,11.33 42.79,11.6 46.22,15.02 46.22,17.33 45.78,17.77 45.78,19.61 46.86,20.68 v1(46.86,24.34)
  BOTTOM w0.112: RT71.2 52.88,24.09 v1(52.88,24.52)
FM_EXT_PWR_MODE: length 38
  TOP w0.127: UT7.AF22 v1(38.78,25.61)
  L5-SIG w0.076: v1(38.78,25.61) 39.59,24.8 40.35,24.8 40.86,24.29 40.86,21.19 41.01,21.04 41.01,14.5 41.65,13.86 41.65,12.35 41.22,11.92 40.77,11.92 40.66,11.8 40.66,11 40.89,10.78 41.12,10.78 41.45,10.44 41.45,8.24 41.08,7.87 41.08,6.83 40.5,6.25 37.71,6.25 36.64,5.18 34.65,5.18 34.31,4.84 34.31,4.14 34.61,3.83 34.61,2.99 34.38,2.75 30.9,2.75 30.72,2.93 v1(30.72,3.29)
  BOTTOM w0.112: JT3.118 30.68,3.25 v1(30.72,3.29)
FM_FAN0_PRSNT_N: length 20.1
  TOP w0.127: v1(15.97,12.91) 15.57,12.91 15.44,13.04 EUT1.1
  L3-SIG w0.076: v1(15.97,12.91) 15.84,12.91 15.66,12.73 15.66,12.21 15.67,12.19 15.67,7.47 16.21,6.92 16.32,6.92 16.57,6.67 16.57,6.22 17.13,5.66 17.89,5.66 19.07,4.48 23.06,4.48 23.51,4.93 v1(23.77,4.93)
  BOTTOM w0.112: JT3.94 24.68,2.58 24.56,2.7 24.56,2.76 24.31,3.01 24.31,4.41 24.08,4.63 24.07,4.63 23.78,4.93 v1(23.77,4.93)
FM_FAN1_PRSNT_N: length 20.9
  TOP w0.127: v1(16.05,12.37) 16.12,12.45 16.12,12.45 16.38,12.71 16.38,13.29 15.89,13.77 15.84,13.77 15.72,13.89 EUT1.2
  L3-SIG w0.076: v1(16.05,12.37) 15.89,12.21 15.89,7.99 16.12,7.75 16.48,7.75 16.78,7.45 16.78,6.33 17.21,5.9 18.11,5.9 18.71,5.29 22.37,5.29 22.47,5.39 23.91,5.39 v1(24.33,4.97)
  BOTTOM w0.112: JT3.96 25.22,1.61 25.22,3.39 24.58,4.03 24.58,4.72 v1(24.33,4.97)
FM_FAN2_PRSNT_N: length 22.5
  TOP w0.127: EUT1.3 15.89,14.39 16.1,14.18 16.1,13.93 16.63,13.4 16.63,13.39 16.67,13.35 16.67,12.44 16.45,12.22 16.45,11.89 16.42,11.86 v1(16.42,11.47)
  L3-SIG w0.076: v1(24.95,4.86) 24.68,5.12 24.68,5.3 23.85,6.13 20.24,6.13 19.65,5.54 18.76,5.54 18.18,6.12 17.29,6.12 17.09,6.33 17.09,7.17 17.36,7.44 17.36,11.09 16.98,11.47 v1(16.42,11.47)
  BOTTOM w0.112: JT3.98 25.68,2.92 25.49,3.1 25.49,4.4 25.04,4.86 v1(24.95,4.86)
FM_FAN3_PRSNT_N: length 22.4
  TOP w0.127: v1(16.88,11.89) 16.88,12.3 16.92,12.34 16.92,13.48 16.35,14.05 16.35,14.67 16.14,14.89 EUT1.4
  L3-SIG w0.076: v1(26.16,3.9) 25.55,4.51 25.55,4.91 24,6.46 20.26,6.46 19.73,5.92 18.79,5.92 18.51,6.2 18.51,6.99 17.6,7.9 17.6,11.31 17.01,11.89 v1(16.88,11.89)
  BOTTOM w0.112: v1(26.16,3.9) 25.77,3.51 25.77,3.18 26.18,2.78 JT3.100
FM_FAN4_PRSNT_N: length 22.3
  TOP w0.127: EUT1.5 16.07,15.39 16.81,14.65 v1(16.81,14.23)
  L3-SIG w0.076: v1(26.16,4.7) 24.07,6.79 20.34,6.79 19.98,7.14 19.98,12.2 19.73,12.45 19.4,12.45 19.17,12.68 19.17,12.98 18.89,13.26 18.56,13.26 18.33,13.49 18.33,13.95 17.92,14.37 17.62,14.37 17.46,14.2 17.21,14.2 17.18,14.23 v1(16.81,14.23)
  BOTTOM w0.112: JT3.102 26.68,2.84 26.59,2.93 26.59,4.27 v1(26.16,4.7)
FM_FAN5_PRSNT_N: length 21.5
  TOP w0.203: EUT1.6 v1(15.44,16.37)
  L3-SIG w0.076: v1(26.99,4.7) 23.13,8.57 23.13,9.75 22.92,9.96 22.65,9.96 22.33,10.28 22.33,10.55 22.12,10.76 21.85,10.76 21.56,11.05 21.56,11.35 20.44,12.46 20.23,12.46 20.03,12.66 20.03,12.88 19.65,13.25 19.43,13.25 19.22,13.46 19.22,13.68 18.93,13.97 18.64,13.97 17.84,14.77 17.41,14.77 15.81,16.37 v1(15.44,16.37)
  BOTTOM w0.112: v1(26.99,4.7) 26.99,4.32 26.87,4.2 26.87,3.03 27.18,2.72 JT3.104
FM_FAN6_PRSNT_N: length 23.3
  TOP w0.203: EUT1.7 14.81,16.69 14.98,16.87 15.38,16.87 15.41,16.91 v1(15.42,16.91)
  L3-SIG w0.076: v1(15.42,16.91) 15.99,16.91 16.32,16.58 16.33,16.58 16.74,16.18 16.74,15.85 17.04,15.55 18.18,15.55 18.44,15.29 18.44,15.05 18.7,14.79 19.75,14.79 20.01,14.53 20.01,13.72 20.53,13.2 20.53,13.15 20.83,12.85 20.83,12.66 21.93,11.56 22.12,11.56 22.43,11.25 22.43,11.06 22.63,10.86 22.82,10.86 23.23,10.45 23.23,10.26 23.53,9.96 23.72,9.96 27.48,6.2 27.48,4.85 v1(27.78,4.55)
  BOTTOM w0.112: JT3.106 27.68,2.88 27.77,2.97 27.77,4.54 v1(27.78,4.55)
FM_FAN7_PRSNT_N: length 31
  TOP w0.203: EUT1.8 v2(14.31,17.3)
  L3-SIG w0.076: v2(14.31,17.3) 14.31,16.32 15.21,15.42 15.21,12.53 15.41,12.32 15.41,7.4 15.79,7.02 15.79,5.26 16.06,4.98 16.73,4.98 16.83,5.09 17.2,5.09 17.21,5.09 17.53,5.09 17.53,5.09 17.62,5.09 18.54,4.17 22.65,4.17 23.33,3.5 23.98,3.5 24.15,3.66 25.01,3.66 25.7,2.97 26.34,2.97 26.61,3.24 26.61,3.49 27.28,4.16 v1(28.48,4.16)
  BOTTOM w0.112: v1(28.48,4.16) 28.12,4.16 28,4.04 28,3.08 28.18,2.9 JT3.108
FM_FORCE_BMC_UPDATE_N: length 35.6
  TOP w0.104: JT3.105 27.43,2.68 27.66,2.9 27.66,3.47 27.75,3.56 27.75,4.04 27.4,4.39 27.4,4.87 v1(27.01,5.26)
  TOP w0.127: UT7.AE24 v1(37.98,27.21)
  L5-SIG w0.076: v1(37.98,27.21) 37.76,27.21 37.13,26.57 36.26,26.57 35.7,26.02 35.3,26.02 34.42,25.13 34.42,22.33 34.08,22 33.67,22 33.58,21.91 33.58,21.46 33.3,21.17 32.93,21.17 32.82,21.06 32.82,20.43 31.9,19.51 31.01,19.51 30.37,18.88 30.37,17.36 30.53,17.2 31.07,17.2 31.18,17.09 31.18,16.59 31.34,16.44 31.66,16.44 31.94,16.16 31.94,15.82 30.9,14.79 29.66,14.79 29.18,14.31 29.18,7.59 27.38,5.79 27.38,5.63 v1(27.01,5.26)
FM_FRU_A2: length 3.2
  BOTTOM w0.112: RB86.2 RB94.1 46.64,21.43 46.52,21.31 UB5.3
FM_HPS_PORSEL: length 2.6
  TOP w0.127: UT7.E18 v1(21.18,22.41)
  BOTTOM w0.254: v1(21.18,22.41) 21.77,21.81 RB99.2 21.94,22.7 RB89.1
FM_IM_MASTER: length 73.6
  TOP w0.104: v1(29.71,3.71) 30.07,3.35 30.07,3.34 30.11,3.3 30.11,2.92 29.93,2.74 JT3.115
  TOP w0.127: UT4.F11 v1(53.38,29.52)
  L3-SIG w0.076: v1(29.71,3.71) 30.98,2.44 34.94,2.44 35.72,3.22 35.72,3.39 35.72,3.4 35.72,3.73 36.06,4.07 36.37,4.07 37.57,5.28 40.93,5.28 41.81,4.39 41.81,2.36 42.87,1.3 58.9,1.3 60.26,2.67 60.26,3.31 v1(59.89,3.69)
  L8-SIG w0.076: v1(53.38,29.52) 54.02,28.88 54.53,28.88 55.14,28.28 55.14,27.21 57.86,24.48 57.86,21.99 59.35,20.5 61.54,20.5 62.1,19.94 62.1,13.11 59.1,10.11 59.1,9.28 58.15,8.33 58.15,5.81 59.89,4.08 v1(59.89,3.69)
FM_JTAG_MUX_SEL: length 34.6
  TOP w0.104: v1(45.99,43.31) 45.99,42.93 45.13,42.07 45.13,32.6 43.23,30.69 43.23,29.83 43.2,29.8 RT24.2 42.89,29.46 42.88,29.45 ST1.4
  L3-SIG w0.076: v1(45.99,43.31) 46.22,43.54 46.22,44.63 46.91,45.32 48.94,45.32 49.62,46 54.79,46 v1(55.24,45.55)
  BOTTOM w0.112: UB3.6 54.04,44.18 54.15,44.28 54.15,45.32 54.37,45.55 v1(55.24,45.55) ; UB2.6 54.04,48.24 54.2,48.09 54.2,47.4 55.24,46.36 v1(55.24,45.55) ; v1(55.24,45.55) 55.4,45.71 U12.1
FM_JTAG_MUX_SEL_SW: length 4.3
  TOP w0.104: ST1.2 42.88,19.83 43.17,19.54 43.17,19.41 43.4,19.18 RT60.2
FM_LED_AMBER_GATE: length 4.9
  TOP w0.104: v1(66.22,33.89) 65.88,33.55 RT42.1 65.47,33.3 65.25,33.53 63.37,33.53 UT4.K2
  BOTTOM w0.112: QB1.2 66.17,33.84 v1(66.22,33.89)
FM_LED_BEEP_BMC: length 15.1
  TOP w0.104: JT3.129 33.43,3.95 33.67,4.2 33.67,4.98 33.09,5.57 33.09,5.69 33.09,5.69 33.09,6.01 33.09,6.01 33.09,7.17 v1(33.24,7.33)
  TOP w0.127: v1(37.98,11.2) 37.98,11.59 38.01,11.63 38.01,11.76 38.1,11.85 38.1,12.13 UT7.AF6
  BOTTOM w0.089: v1(37.98,11.2) 37.45,11.2 36.24,9.99 33.86,9.99 33.62,9.75 33.62,8.74 33.24,8.36 33.24,7.65
  BOTTOM w0.112: 33.24,7.65 v1(33.24,7.33)
FM_LED_GREEN_GATE: length 8.2
  TOP w0.127: UT4.K5 v1(60.38,34.52)
  L3-SIG w0.076: v1(65.37,36) 64.53,36 63.54,35.01 60.87,35.01 v1(60.38,34.52)
  BOTTOM w0.112: v1(65.37,36) 65.58,35.79 RB68.1 66.17,35.78 QB1.5
FM_M10_CONFIG_SEL: length 2.3
  TOP w0.127: UT4.F8 v1(57.38,29.52)
  BOTTOM w0.112: v1(57.38,29.52) 57.29,29.43 RB85.1 55.95,29.43 RB87.2
FM_M10_DEBUG_0: length 53.2
  TOP w0.104: v1(54.43,38.49) 53.89,39.02 UT4.R11 ; v1(67.33,40.11) 66.39,40.11 64.99,41.51 JT1.9
  TOP w0.127: v1(33.22,24.85) UT7.W21
  L3-SIG w0.076: v1(67.33,40.11) 65.25,38.03 54.88,38.03 v1(54.43,38.49)
  L10-SIG w0.076: v1(54.43,38.49) 54.93,37.98 55.54,37.98 56.81,36.71 56.81,35.16 56.56,34.91 54.27,34.91 53.36,33.99 49.62,33.99 44.42,28.78 44.42,28.43 40.44,24.45 33.53,24.45 33.22,24.77 v1(33.22,24.85)
FM_M10_DEBUG_1: length 48.2
  TOP w0.104: UT4.R12 52.88,39.02 v1(52.44,38.59) ; JT1.11 66.26,41.33 66.85,40.75 v1(67.35,40.75)
  TOP w0.127: UT7.AA23 v1(34.78,26.41)
  L3-SIG w0.076: v1(67.35,40.75) 66.98,40.75 65.2,38.97 52.8,38.97 52.44,38.61 v1(52.44,38.59)
  L10-SIG w0.076: v1(34.78,26.41) 34.36,26.83 34.36,28.88 34.67,29.19 38.45,29.19 39.24,29.98 39.24,30.68 39.71,31.15 42.49,31.15 44.3,32.96 44.3,37 45.88,38.58 47.51,38.58 47.87,38.94 51.66,38.94 52.01,38.59 v1(52.44,38.59)
FM_M10_DEBUG_2: length 59.9
  TOP w0.089: UT7.V15 v1(31.6,19.99)
  TOP w0.104: JT1.13 67.53,41.53 v1(67.38,41.38) ; v1(52.37,40.53) UT4.T12
  L3-SIG w0.076: v1(52.37,40.53) 52.89,40.01 65.53,40.01 66.9,41.38 v1(67.38,41.38)
  L10-SIG w0.076: v1(52.37,40.53) 51.79,40.53 50.51,39.25 47.36,39.25 47.12,39.01 45.29,39.01 43.91,37.62 43.91,33.38 43.66,33.13 43.27,33.13 42.87,32.72 37.08,32.72 36.32,31.96 36.32,31.2 35.22,30.1 34.23,30.1 33.85,29.72 33.85,29.7 32.61,28.45 32.33,28.45 31.98,28.1 31.98,23.95 32.36,23.58 34.26,23.58 34.41,23.42 34.41,21.14 33.7,20.43 32.78,20.43 32.34,19.99 v1(31.6,19.99)
FM_M10_DEV_CLR_N: length 2.2
  TOP w0.127: UT4.B10 v1(54.38,25.52)
  BOTTOM w0.112: RB101.2 55.02,24.88 v1(54.38,25.52)
FM_M10_EDGE_RSVD<2>: length 68.1
  TOP w0.104: v1(64.41,35.13) 64.29,35.02 UT4.L1
  L8-SIG w0.076: v1(64.41,35.13) 64.02,34.74 64.02,33.82 66.6,31.24 66.6,30.12 66.62,30.1 66.62,23.38 65.73,22.48 65.73,21.21 67,19.94 67,17.59 67.16,17.43 67.16,15.35 65.98,14.17 65.98,12.1 66.62,11.45 66.62,8.72 66.13,8.24 66.13,4.73 66.57,4.3 66.57,2.44 64.93,0.81 43.96,0.81 42.3,2.47 42.3,3.83 41.92,4.2 41.08,4.2 v1(41.02,4.14)
  BOTTOM w0.112: JT3.148 40.18,2.92 40.18,3.51 40.43,3.76 40.59,3.76 40.6,3.77 40.66,3.77 40.87,3.99 40.87,3.99 v1(41.02,4.14)
FM_M10_EDGE_RSVD<3>: length 69.3
  TOP w0.104: v1(63.39,35.58) 62.88,35.07 UT4.L2
  L8-SIG w0.076: v1(41.45,3.82) 41.83,3.82 42.06,3.59 42.06,2.37 43.86,0.57 65.04,0.57 66.81,2.33 66.81,4.59 66.38,5.02 66.38,7.13 67.07,7.83 67.07,8.42 66.87,8.63 66.87,11.56 66.36,12.07 66.36,14.1 67.37,15.11 67.37,15.22 67.4,15.25 67.4,17.53 67.24,17.69 67.24,20.08 66.67,20.66 66.67,21.95 66.87,22.15 66.87,30.2 66.84,30.22 66.84,31.57 65.42,32.99 65.42,35.35 65.2,35.58 v1(63.39,35.58)
  BOTTOM w0.112: JT3.150 40.68,2.75 40.48,2.95 40.48,2.99 40.47,2.99 40.47,3.31 40.7,3.54 41.09,3.54 41.32,3.76 41.4,3.76 v1(41.45,3.82)
FM_M10_EDGE_RSVD<4>: length 43.3
  TOP w0.104: v1(61.45,35.45) UT4.L3
  L5-SIG w0.076: v1(51.35,6.38) 50.95,6.38 50.38,6.95 50.38,10.55 50.06,10.88 50.06,11.93 50.27,12.15 50.27,13.37 52.23,15.32 55.16,15.32 55.85,16.01 55.85,17.61 58.34,20.1 58.34,22.08 58.85,22.59 59.28,22.59 60.83,24.14 60.83,28.66 62.7,30.53 62.7,33.18 61.79,34.09 61.79,35.11 v1(61.45,35.45)
  BOTTOM w0.112: v1(51.35,6.38) 50.82,5.85 50.82,3.08 50.68,2.94 JT3.190
FM_M10_EDGE_RSVD<5>: length 42.6
  TOP w0.104: UT4.M3 v1(62.36,35.54)
  L5-SIG w0.076: v1(62.36,35.54) 62.45,35.54 62.74,35.26 62.74,33.98 62.99,33.74 62.99,30.49 61.74,29.24 61.74,26.67 61.75,26.66 61.75,26.05 61.59,25.89 61.59,25.3 61.13,24.85 61.13,23.75 59.61,22.23 59,22.23 58.59,21.82 58.59,19.82 56.18,17.4 56.18,15.89 55.2,14.92 52.77,14.92 52.1,14.24 52.1,12.62 52.44,12.27 52.44,9.39 52.44,9.39 52.44,8.67 52.62,8.49 52.62,7.14 52.31,6.83 52.31,5.98 51.83,5.5 51.83,4.47 51.74,4.37 v1(51.35,4.37)
  BOTTOM w0.112: JT3.192 51.18,2.66 51.68,3.16 51.68,4.04 v1(51.35,4.37)
FM_M10_EDGE_RSVD<6>: length 49.7
  TOP w0.104: UT4.L6 v1(59.38,35.52)
  L5-SIG w0.076: v1(59.38,35.52) 59.86,36 62.47,36 62.98,35.48 62.98,34.23 64.13,33.08 64.13,30.94 63.01,29.83 63.01,28.46 63.05,28.43 63.05,26.31 62.86,26.12 62.43,26.12 61.87,25.56 61.87,25.13 61.49,24.75 61.49,23.09 62.69,21.89 62.69,20.9 62.1,20.3 62.1,19.16 61.49,18.55 57.93,18.55 56.48,17.1 56.48,15.86 55.21,14.59 52.9,14.59 52.36,14.04 52.36,12.7 52.85,12.21 52.85,10.19 53.23,9.81 53.23,6.09 52.43,5.29 v1(52.43,4.75)
  BOTTOM w0.112: JT3.194 51.71,1.6 51.71,2.85 51.94,3.08 51.94,3.43 51.94,3.43 51.94,4.26 52.05,4.37 52.05,4.38 52.28,4.6 52.28,4.6 v1(52.43,4.75)
FM_M10_EDGE_RSVD<7>: length 47.6
  TOP w0.104: v1(63.39,36.53) 62.88,36.02 UT4.M2
  L5-SIG w0.076: v1(63.39,36.53) 63.82,36.1 63.82,34.22 64.43,33.62 64.43,28.68 63.95,28.2 63.95,26.61 61.79,24.46 61.79,23.14 63.06,21.87 63.06,20.96 62.45,20.35 62.45,18.17 61.49,17.2 57.37,17.2 56.74,16.57 56.74,15.75 55.31,14.33 55.31,13.95 53.46,12.1 53.46,10.67 53.71,10.42 53.71,6.83 54.43,6.11 54.43,5.75 54.92,5.25 54.92,4.78 54.71,4.56 54.39,4.56 54.18,4.36 54.18,3.9 54.07,3.79 53.25,3.79 52.83,4.22 v1(52.44,4.22)
  BOTTOM w0.112: JT3.196 52.18,2.88 52.18,2.89 52.18,3.01 52.17,3.01 52.17,3.33 52.18,3.33 52.18,3.95 v1(52.44,4.22)
FM_M10_JTAGEN: length 20.4
  TOP w0.104: v1(44.75,31.04) 44.06,31.04 43.81,30.79 43.81,29.9 43.86,29.85 RT25.1 44.16,29.43 44.15,29.42 ST1.3
  TOP w0.127: UT4.G6 v1(59.38,30.52)
  L3-SIG w0.076: v1(59.38,30.52) 58.9,31 58.9,31.6 58.62,31.88 48.18,31.88 47.85,31.54 47.85,31.53 47.36,31.04 v1(44.75,31.04)
FM_M10_JTAGEN_SW: length 2.2
  TOP w0.104: ST1.1 45.28,20.99 45.73,20.54 RT58.2
FM_P0V75_AUX_EN_R: length 2.1
  BOTTOM w0.254: EU8F1.7 47.69,46.06 47.24,46.51 C8F8.1 R8F8.2
FM_P3V3_AUX_IO_G: length 2.3
  TOP w0.104: CT14.1 2.44,23.91 RT50.2 2.13,24.86 2.13,25.3 2.32,25.5 UT3.3
FM_PCH_BMC_THERMTRIP_N: length 26.2
  TOP w0.104: JT3.35 9.93,2.92 9.52,3.33 9.52,3.67 9.14,4.04 v1(9.14,4.04)
  TOP w0.127: UT7.A17 v1(17.98,21.61)
  L8-SIG w0.076: v1(17.98,21.61) 17.98,21.75 17.75,21.98 17.27,21.98 16.17,20.88 15.16,20.88 13.63,19.36 13.63,17.15 13.61,17.13 13.61,17.12 11.62,15.13 11.62,13.09 10.81,12.29 10.81,12.03 10.14,11.36 10.14,7.57 9.32,6.75 9.32,4.22 v1(9.14,4.04)
FM_PGPPA_AUX_IO_G: length 3
  TOP w0.104: UT2.3 15.83,28.18 15.09,27.45 RT39.2 CT10.1
FM_PVCCIN_CPU0_PWR_IN_ALERT_N: length 49.2
  TOP w0.127: v1(40.81,26.04) 41.09,25.76 41.09,24.87 40.63,24.41 UT7.AH21
  L8-SIG w0.076: v1(40.81,26.04) 36.21,26.04 36.04,25.86 36.04,25.41 35.84,25.21 29.41,25.21 28.64,24.44 28.3,24.44 27.96,24.1 27.96,23.81 27.73,23.58 27.44,23.58 27.15,23.29 27.15,19.79 27,19.65 26.59,19.65 25.83,18.88 23.49,18.88 21.58,16.97 21.58,15.75 21.41,15.58 21.03,15.58 20.75,15.29 20.75,14.92 20.62,14.79 20.25,14.79 19.96,14.5 19.96,14.18 19.82,14.04 18.65,14.04 18.37,13.76 18.37,10.05 17.53,9.21 17.53,8.08 17.18,7.73 17.13,7.73 17.12,7.72 16.28,7.72 16,7.43 16,6.46 v1(16.17,6.28)
  BOTTOM w0.112: JT3.72 19.18,4.14 17.93,5.39 17.14,5.39 16.25,6.28 v1(16.17,6.28)
FM_PVCCIN_CPU1_PWR_IN_ALERT_N: length 32.9
  TOP w0.104: JT3.117 30.43,2.88 30.35,2.97 30.35,3.13 30.34,3.13 30.34,3.72 30.13,3.93 v1(30.13,4.83)
  TOP w0.127: UT7.AD23 v1(37.18,25.61)
  L5-SIG w0.076: v1(37.18,25.61) 37.59,25.2 37.59,24.54 37.46,24.41 36.98,24.41 36.74,24.18 36.74,19.31 36.37,18.94 36.37,14.16 35.78,13.58 35.78,13.19 35.15,12.55 35.15,10.27 35.43,9.99 35.73,9.99 35.99,9.73 35.99,8.54 36.29,8.24 36.29,7.52 36.09,7.33 34.55,7.33 34.32,7.55 33.62,7.55 33.32,7.85 31.42,7.85 30.91,7.34 30.91,6.82 30.13,6.03 v1(30.13,4.83)
FM_SI5338_SMB_A0: length 1.6
  TOP w0.104: EU5C1.3 48.99,11.84 48.86,11.97 v1(48.86,12.03)
  BOTTOM w0.112: v1(48.86,12.03) 48.86,11.27 R5C13.1
FM_SKT0_FAULT_LED: length 117
  TOP w0.127: v1(47.31,33.53) 49.4,33.53 UT4.K15
  L5-SIG w0.076: v1(10.59,4.17) 10.84,4.17 10.97,4.04 10.97,3.26 10.69,2.98 6.98,2.98 6.62,3.33 6.62,5.23 4.41,7.44 4.41,9.92 5.48,10.99 5.48,14.71 5.99,15.22 5.99,17.2 7.29,18.5 7.29,19.43 6.86,19.86 6.86,24.54 5.86,25.53 5.86,26.4 4.65,27.61 4.65,31.8 3.27,33.18 3.27,46.69 4.11,47.53 46.1,47.53 47,46.63 47,38.54 46.37,37.92 46.37,36.63 46.98,36.02 46.98,34.54 46.9,34.46 46.9,34.14 46.98,34.05 46.98,33.86 v1(47.31,33.53)
  BOTTOM w0.112: v1(10.59,4.17) 10.83,4.17 10.94,4.06 10.94,3.15 10.68,2.88 JT3.38
FM_SLPS4_N: length 29.5
  TOP w0.127: UT7.AE23 v1(37.98,26.41)
  L5-SIG w0.076: v1(37.98,26.41) 37.56,25.99 37,25.99 36.8,25.79 36.8,24.57 36.53,24.3 36.53,20.82 35.96,20.25 35.96,14.18 35.48,13.7 35.48,13.32 34.36,12.2 34.36,10.21 34.56,10.01 34.88,10.01 35.17,9.73 35.17,8.44 v1(35.91,7.7)
  L5-SIG w0.089: 37.98,26.4 v1(37.98,26.41)
  BOTTOM w0.112: v1(35.91,7.7) 35.53,7.33 35.04,7.33 34.77,7.05 34.77,6.65 34.61,6.49 34.61,4.48 34.95,4.14 35.28,4.14 35.66,3.76 35.66,3.43 35.67,3.43 35.67,2.9 35.67,2.89 35.67,2.83 35.68,2.82 JT3.138
FM_SW_ON: length 60.5
  TOP w0.104: v1(27.86,5.09) 28.16,4.78 28.16,4.39 27.98,4.21 27.98,3.47 27.89,3.37 27.89,2.81 27.83,2.75 27.83,1.67 JT3.107
  TOP w0.127: UT4.E11 v1(53.38,28.52)
  L5-SIG w0.076: v1(27.86,5.09) 27.77,5.09 27.39,4.71 27.39,4.29 26.89,3.78 26.89,3.02 27.63,2.27 35.15,2.27 35.68,2.8 35.68,3.89 35.88,4.09 36.28,4.09 37.35,5.17 37.82,5.64 41.55,5.64 42.46,4.73 42.46,2.72 42.64,2.55 43.28,2.55 43.53,2.8 43.53,5.58 45.03,7.08 45.03,13.62 48.84,17.43 49.55,17.43 50.58,18.46 50.58,21.07 51.8,22.3 51.8,22.74 51.83,22.77 51.83,24.23 51.86,24.26 51.86,24.57 50.92,25.51 50.92,27.67 51.28,28.02 52.88,28.02 v1(53.38,28.52)
FM_TPM_EN_PULSE: length 22.6
  TOP w0.104: v1(24.71,3.2) 24.43,2.93 JT3.93
  TOP w0.127: UT7.AH4 v1(39.56,10.39)
  L8-SIG w0.076: v1(39.56,10.39) 39.14,9.97 38.63,9.97 38.37,9.72 38.37,9.4 38.12,9.15 34.64,9.15 34.63,9.15 34.61,9.15 34.42,8.96 34.42,8.73 34.13,8.45 33.76,8.45 32.81,7.5 32.81,6.99 32.23,6.41 30.93,6.41 29.71,5.19 29.71,4.6 29.3,4.2 29.3,2.72 29.04,2.46 25.46,2.46 v1(24.71,3.2)
FM_USB2A_PWREN: length 3.9
  TOP w0.104: JT3.213 56.43,2.91 56.28,3.05 56.28,3.15 56.28,3.15 56.28,4.83 56.13,4.98 R390.2
FM_USBPHY_PCH_CPEN: length 6.8
  TOP w0.104: U8A6.17 59.83,8.57 60,8.4 60,8.25 v1(59.58,7.83) ; v1(56.38,6.48) 56.13,6.23 R390.1
  L10-SIG w0.076: v1(59.58,7.83) 56.28,7.83 55.96,7.51 55.96,6.9 v1(56.38,6.48)
FM_USBPHY_PCH_ID: length 1.5
  TOP w0.104: U8A6.23 60.22,11.57 60.68,11.11 R7A54.2
FM_USBPHY_USB2B_CPEN: length 1.6
  TOP w0.104: EU12.17 62.81,16.31 63.04,16.08 63.11,16.08 v1(63.29,15.91)
  BOTTOM w0.112: v1(63.29,15.91) 63.47,16.08 R412.1
FM_USBPHY_USB2B_ID: length 1.3
  TOP w0.104: v1(63.31,19.36) 63.27,19.31 EU12.23
  BOTTOM w0.112: v1(63.31,19.36) 63.29,19.33 R396.2
FM_VGA_B<0>: length 16.1
  TOP w0.104: R424.1 v1(52.93,22.66)
  TOP w0.127: UT7.AG19 v1(39.58,23.21)
  L3-SIG w0.076: v1(39.58,23.21) 39.99,23.62 40.58,23.62 40.65,23.68 42.8,23.68 43.64,22.84 48.1,22.84 48.86,22.08 50.55,22.08 51.05,22.58 51.05,22.85 51.14,22.94 52.65,22.94 v1(52.93,22.66)
FM_VGA_B<1>: length 21
  TOP w0.104: v1(53.69,22.64) R420.1
  TOP w0.127: UT7.AD20 v1(37.18,24.01)
  L3-SIG w0.076: v1(53.69,22.64) 53.64,22.64 53.51,22.76 53.51,24.69 53.07,25.14 43.84,25.14 43.55,24.85 42.64,24.85 42.23,25.26 37.84,25.26 37.52,24.93 37.52,24.35 v1(37.18,24.01)
FM_VGA_B<2>: length 13.2
  TOP w0.104: R423.1 v1(51.4,22.51)
  TOP w0.127: UT7.AH19 v1(40.38,23.21)
  L3-SIG w0.076: v1(51.4,22.51) 50.74,21.85 48.66,21.85 47.87,22.64 43.53,22.64 42.7,23.47 40.64,23.47 v1(40.38,23.21)
FM_VGA_B<3>: length 15.2
  TOP w0.104: R417.1 v1(52.16,22.59)
  TOP w0.127: UT7.AG18 v1(39.58,22.41)
  L3-SIG w0.076: v1(39.58,22.41) 39.64,22.41 40.1,22.86 40.66,22.86 41.04,23.25 42.46,23.25 43.27,22.43 47.67,22.43 48.53,21.57 51.15,21.57 v1(52.16,22.59)
FM_VGA_G<0>: length 30.9
  TOP w0.104: R428.1 51.91,19.91 51.91,20.35 52.09,20.53 v1(52.24,20.53)
  TOP w0.127: UT7.AA19 v1(34.78,23.21)
  L3-SIG w0.076: v1(52.24,20.53) 53.05,20.53 54.29,21.77 54.29,24.75 53.84,25.2 53.84,26.7 53.59,26.95 43.76,26.95 43.3,26.5 40.18,26.5 39.69,26.02 37.05,26.02 36.75,25.71 36.75,24.14 36.16,23.55 35.12,23.55 v1(34.78,23.21)
FM_VGA_G<1>: length 14.2
  TOP w0.104: R422.1 50.95,19.82 51.3,20.17 51.3,20.33 v1(51.5,20.53)
  TOP w0.127: UT7.AH18 v1(40.38,22.41)
  L3-SIG w0.076: v1(51.5,20.53) 51.5,20.53 51.48,20.55 51.48,21.11 51.28,21.32 48.53,21.32 47.62,22.23 43.12,22.23 42.44,22.92 41.01,22.92 40.51,22.41 v1(40.38,22.41)
FM_VGA_G<2>: length 28.5
  TOP w0.104: R427.1 50.08,20.3 50.29,20.5 v1(50.97,20.5)
  TOP w0.127: UT7.AA18 34.78,22.41 35.43,22.41 v1(35.45,22.38)
  L3-SIG w0.076: v1(35.45,22.38) 35.81,22.38 37.09,23.66 37.32,23.66 38.12,24.47 38.63,24.47 38.64,24.46 38.96,24.46 39.5,25.01 42.15,25.01 42.54,24.62 43.61,24.62 43.92,24.94 47.55,24.94 47.58,24.96 52.93,24.96 53.27,24.62 53.27,22.52 53.07,22.32 53.04,22.32 51.89,21.16 51.89,20.14 51.81,20.06 51.05,20.06 50.97,20.14 v1(50.97,20.5)
FM_VGA_G<3>: length 14.6
  TOP w0.104: R419.1 49.5,20.06 49.5,20.3 49.65,20.45 v1(49.73,20.45)
  TOP w0.127: UT7.AE19 v1(37.98,23.21)
  L3-SIG w0.076: v1(37.98,23.21) 38.29,23.21 38.75,22.75 39.03,22.75 39.23,22.55 39.23,22.27 39.45,22.05 40.96,22.05 41.14,21.87 43.05,21.87 43.2,22.03 47.52,22.03 47.78,21.76 47.79,21.76 48.51,21.04 49.14,21.04 v1(49.73,20.45)
FM_VGA_R<0>: length 16.9
  TOP w0.104: R426.1 v1(50.51,22.54)
  TOP w0.127: UT7.AF18 v1(38.78,22.41)
  L3-SIG w0.076: v1(38.78,22.41) 38.43,22.75 37.95,22.75 37.63,23.07 37.63,23.35 38.12,23.83 38.83,23.83 39.41,24.41 40.5,24.41 40.95,23.96 40.97,23.96 41,23.93 45.92,23.93 46.42,23.42 49.62,23.42 v1(50.51,22.54)
FM_VGA_R<1>: length 14.6
  TOP w0.104: R421.1 48.23,23.63 v1(48.38,23.78)
  TOP w0.127: UT7.AD19 v1(37.18,23.21)
  L3-SIG w0.076: v1(37.18,23.21) 38.28,24.31 38.57,24.31 38.57,24.31 39.07,24.31 39.4,24.64 40.57,24.64 41.08,24.14 46.16,24.14 46.52,23.78 v1(48.38,23.78)
FM_VGA_R<2>: length 10.9
  TOP w0.104: R425.1 v1(49.75,22.54)
  TOP w0.127: UT7.AH17 v1(40.38,21.61)
  L10-SIG w0.076: v1(49.75,22.54) 49.35,22.14 44.42,22.14 44.21,21.93 40.96,21.93 40.65,21.61 v1(40.38,21.61)
FM_VGA_R<3>: length 18
  TOP w0.104: R418.1 v1(48.99,22.56)
  TOP w0.127: UT7.Y15 v1(33.98,20.01)
  L10-SIG w0.076: v1(48.99,22.56) 48.84,22.41 42.79,22.41 42.41,22.79 36.54,22.79 35.22,21.47 35.22,20.6 35.02,20.4 34.37,20.4 v1(33.98,20.01)
